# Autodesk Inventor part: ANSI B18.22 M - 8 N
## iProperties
Comments: To add or edit properties for Autodesk Inventor files, use iProperties.
Created: 2004-08
Part Number: ANSI B18.22 M - 8 N
Vendor: Autodesk Inc.
Document SubType Name: Modeling
Designer: John Blackburn
Material: Default
Description: Plain Washer
Standard: ANSI B18.22 M
Size Designation: 8 N
Alert: To add or edit properties for Autodesk Inventor files, use iProperties.
Control State: 0
Master: False
Checked Out: False
Shininess: 64.0
Length Units: 11269
Angle Units: 11279
Time Units: 11290
Mass Units: 11283
Length Display Precision: 3
Angle Display Precision: 2
Compacted: True
Classification: un/spsc 31161807
Density: 0.0
Volumn: 0.0
Area: 0.0
PropertySet Name: Model Information
Author: John Blackburn
Revision Number: 8
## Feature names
1. Body [Extrusion]
